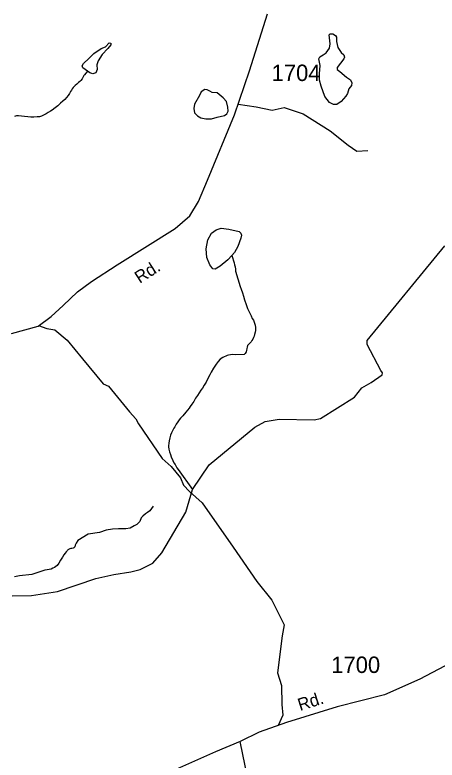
# Model space of a CAD drawing. Extents: x 2056842 to 2160602, y 826753 to 1016856.
# Drawn here: x 2114302 to 2117511, y 858411 to 864081 of the extents above; entities that cross this region are included whole.
import ezdxf

# ---------------------------------------------------------------- set-up
doc = ezdxf.new("R2010")
doc.units = 0
for name, color, linetype in [('Exist Hydrographic Creek Single Shore', 7, 'Continuous'), ('Exist Hydrographic Misc Water Feature', 7, 'Continuous'), ('Exist Road Non-System Type 51', 7, 'Continuous'), ('Exist Road Secondary Type 51 Attributed', 7, 'Continuous'), ('Exist Road Secondary Type 51 Label', 7, 'Continuous'), ('Exist Road Secondary Type 51 Number Label', 7, 'Continuous')]:
    doc.layers.add(name, color=color, linetype=linetype)

msp = doc.modelspace()

# ---------------------------------------------------------------- linework, layer by layer
at = {"layer": 'Exist Hydrographic Creek Single Shore'}
for points in [[(2114281.1, 859660), (2114427.1, 859662.3), (2114625.5, 859693.7), (2114916.8, 859793), (2115054.9, 859823.1), (2115184.3, 859843.2), (2115253.3, 859860.8), (2115350, 859909.8), (2115419.9, 859987.6), (2115601.8, 860298.8), (2115652.6, 860468.9), (2115778.2, 860657.4), (2116126, 860943.8), (2116205.1, 860987.8), (2116310.6, 861004.1), (2116576.8, 860999.1), (2116623.8, 861009.4), (2116883.2, 861173.8), (2116938.4, 861242.9), (2117010, 861284.3), (2117094.1, 861343.4), (2117095.4, 861358.4), (2117082.8, 861376), (2116978.6, 861572), (2116978.9, 861602.5), (2117571.4, 862322.8)], [(2115352.2, 860342.5), (2115327.1, 860308.5), (2115310.8, 860296), (2115294.5, 860285.5), (2115274.4, 860267), (2115260.5, 860254.9), (2115250.5, 860225.6), (2115229.1, 860204.3), (2115209, 860193), (2115177.7, 860175.4), (2115145, 860170.3), (2115088.5, 860171.6), (2115044.6, 860167.8), (2114996.8, 860160.3), (2114945.4, 860143.4), (2114858.7, 860130.9), (2114780.3, 860081.3), (2114766.3, 860061.1), (2114760.6, 860047), (2114756.5, 860035), (2114750.7, 860026.9), (2114745, 860024.6), (2114734.7, 860022.1), (2114726.9, 860020.8), (2114718.7, 860018.4), (2114704.8, 860010.8), (2114700.7, 860006.5), (2114690.9, 859996.2), (2114683.3, 859986.4), (2114673.2, 859971.7), (2114663.4, 859955.8), (2114649.4, 859933.5), (2114635.7, 859909.2), (2114622.2, 859891.9), (2114612.3, 859883.6), (2114602.3, 859877.4), (2114590.2, 859871.1), (2114577.3, 859864.5), (2114563.3, 859860.9), (2114548.1, 859858.8), (2114528.3, 859856.5), (2114430.5, 859822.8), (2114336.4, 859812.8), (2114298.7, 859805.2)]]:
    msp.add_lwpolyline(points, dxfattribs=at)
at = {"layer": 'Exist Hydrographic Misc Water Feature'}
for points in [[(2116816.5, 863463.5), (2116782.1, 863421.5), (2116750.3, 863398.6), (2116724.9, 863398.6), (2116694.3, 863413.9), (2116658.7, 863461), (2116629.4, 863538.7), (2116618, 863584.5), (2116616.7, 863632.9), (2116621.8, 863696.6), (2116612.9, 863746.2), (2116620.5, 863762.8), (2116644.7, 863776.8), (2116667.6, 863793.3), (2116694.3, 863827.7), (2116699.4, 863860.8), (2116691.8, 863928.3), (2116699.4, 863937.2), (2116718.5, 863936), (2116740.1, 863923.2), (2116747.8, 863910.5), (2116747.8, 863878.7), (2116756.7, 863832.8), (2116780.9, 863795.9), (2116802.5, 863778.1), (2116806.3, 863760.2), (2116801.2, 863746.2), (2116751.6, 863680), (2116752.9, 863664.7), (2116771.9, 863649.4), (2116822.9, 863606.1), (2116852.1, 863585.8), (2116862.3, 863565.4), (2116861, 863543.8), (2116840.7, 863518.3), (2116829.2, 863482.6), (2116816.5, 863463.5)], [(2114853.7, 863652.8), (2114817.3, 863679.2), (2114813.5, 863694.3), (2114822.3, 863711.9), (2114863.8, 863748.3), (2114902.7, 863788.5), (2114957.9, 863826.2), (2114989.3, 863837.5), (2115019.5, 863867.7), (2115030.8, 863865.2), (2115032, 863853.9), (2115008.2, 863825), (2114965.5, 863779.7), (2114935.3, 863730.7), (2114924, 863700.6), (2114926.5, 863666.7), (2114917.7, 863641.5), (2114893.9, 863631.5), (2114871.3, 863640.3), (2114853.7, 863652.8)], [(2114853.7, 863652.8), (2114830.7, 863624.5), (2114826.8, 863619.4), (2114821.3, 863609.7), (2114813.1, 863595.9), (2114803.4, 863583.2), (2114795.6, 863575), (2114785.8, 863567.2), (2114771.9, 863555.1), (2114760, 863544.7), (2114749.9, 863534.9), (2114743.8, 863528.5), (2114738.2, 863518.8), (2114731.9, 863509.2), (2114725.5, 863498), (2114716.5, 863482.3), (2114706, 863468.9), (2114694.3, 863452.4), (2114680.2, 863437.9), (2114666, 863424.2), (2114649, 863409.7), (2114627.1, 863389.9), (2114607.4, 863373.8), (2114583.8, 863357.1), (2114571.5, 863349.2), (2114553.7, 863339), (2114539.7, 863329.4), (2114524.6, 863319.9), (2114503.9, 863310.4), (2114488.3, 863305.9), (2114470, 863304.5), (2114445.8, 863304.2), (2114422, 863303.7), (2114399.1, 863304.3), (2114374.1, 863307.3), (2114351.7, 863311.1), (2114330, 863313.3), (2114314, 863313.7), (2114297.8, 863308.7)], [(2115797.2, 863291.3), (2115840.5, 863303.8), (2115896.3, 863315.2), (2115913.3, 863328.9), (2115922.4, 863349.4), (2115920.2, 863377.9), (2115909.9, 863421.2), (2115884.9, 863450.8), (2115840.5, 863487.3), (2115801.7, 863491.8), (2115784.7, 863499.8), (2115764.2, 863511.2), (2115746, 863512.3), (2115718.6, 863495.3), (2115706.1, 863469), (2115666.2, 863403), (2115661.7, 863368.8), (2115667.4, 863335.7), (2115689, 863313), (2115715.2, 863298.1), (2115752.8, 863291.3), (2115797.2, 863291.3)], [(2115950.2, 862250.5), (2115920.1, 862217.8), (2115862.3, 862170.1), (2115823.4, 862147.5), (2115807.1, 862150), (2115783.2, 862178.9), (2115761.9, 862235.4), (2115755.6, 862300.8), (2115768.2, 862368.6), (2115797, 862420.1), (2115830.9, 862446.5), (2115871.1, 862457.8), (2115928.9, 862451.5), (2116005.5, 862433.9), (2116020.5, 862420.1), (2116025.6, 862406.3), (2116020.5, 862381.2), (2115996.7, 862319.6), (2115970.3, 862274.4), (2115950.2, 862250.5)], [(2115950.2, 862250.5), (2115967.7, 862194.8), (2115971.4, 862179.2), (2115975.7, 862163.5), (2115977.8, 862145.4), (2115980, 862131.6), (2116015.3, 862013.5), (2116021, 861995.2), (2116031.5, 861965.7), (2116039.5, 861940), (2116047.9, 861913.7), (2116059.8, 861878.1), (2116070.7, 861846.1), (2116084.8, 861816), (2116098.7, 861790.3), (2116106.7, 861772.1), (2116115.1, 861759), (2116123.4, 861736.6), (2116127.9, 861720.1), (2116129.7, 861702.9), (2116129.7, 861690.7), (2116129.9, 861678.9), (2116127.9, 861667), (2116124, 861650.6), (2116120.3, 861636.4), (2116116.6, 861626.9), (2116110.2, 861614.5), (2116102.4, 861602.7), (2116096.7, 861594.2), (2116086.9, 861583.9), (2116078.9, 861574.2), (2116070.9, 861564.5), (2116067, 861554.1), (2116064.9, 861541.8), (2116063.1, 861527.9), (2116059, 861516.3), (2116053.2, 861504.2), (2116045.4, 861496.1), (2115975.7, 861495.3), (2115957.3, 861497.2), (2115941.7, 861495.2), (2115925.3, 861491.2), (2115916, 861488.9), (2115906, 861485.1), (2115893.7, 861480.5), (2115881.6, 861474.2), (2115861.9, 861460.6), (2115847.8, 861444.4), (2115832.2, 861424.5), (2115812.5, 861393.4), (2115794.9, 861363.6), (2115783.2, 861341.9), (2115769.4, 861315.5), (2115755.3, 861287.2), (2115741.5, 861262.9), (2115727.6, 861241.1), (2115716.1, 861225), (2115702.2, 861204.8), (2115690.3, 861185.4), (2115674.7, 861165.1), (2115660.8, 861140.8), (2115646.8, 861118.2), (2115634.9, 861100.5), (2115627.5, 861088.3), (2115601.5, 861058.1), (2115577.7, 861030.1), (2115561.9, 861013.8), (2115550.2, 860999.3), (2115539.8, 860985.9), (2115528.3, 860966.9), (2115516.4, 860947.7), (2115510.7, 860935.6), (2115502.2, 860921), (2115492.6, 860901.3), (2115484.8, 860882.7), (2115479.5, 860863.2), (2115475.4, 860841), (2115471.5, 860823), (2115469.9, 860802.6), (2115469.9, 860795.2), (2115471.9, 860777.1), (2115476.2, 860756.6), (2115484.4, 860736.7), (2115490.4, 860719.6), (2115502.9, 860689.6), (2115510.7, 860673), (2115519.1, 860659.6), (2115533.4, 860635.5), (2115543.3, 860621.4), (2115652.6, 860468.9)]]:
    msp.add_lwpolyline(points, dxfattribs=at)
at = {"layer": 'Exist Road Non-System Type 51'}
for points in [[(2115998.7, 863402.3), (2116137, 863381.2), (2116257.5, 863356.2), (2116348.9, 863377), (2116494.3, 863327.1), (2116697.8, 863198.3), (2116834.9, 863090.2), (2116901.4, 863044.5), (2116984.4, 863048.6)], [(2114482.3, 861717.4), (2114543.8, 861694.8), (2114606.1, 861684.4), (2114699.6, 861607.5), (2114815.9, 861464.1), (2114971.7, 861272.9), (2115013.2, 861256.3), (2115174.2, 861059.9), (2115222, 861007.9), (2115240.7, 860970.5), (2115421.4, 860706.5), (2115489.9, 860646.2), (2115559.5, 860560), (2115582.3, 860501.8), (2115630.1, 860454), (2115725.6, 860368.8), (2115960.3, 860032.1), (2116140, 859769.1), (2116256.3, 859627.8), (2116349.8, 859440.7), (2116333.2, 859355.5), (2116298.9, 859073.9), (2116328, 858978.3), (2116330.1, 858834.9), (2116338.4, 858751.7), (2116302.7, 858674.7)]]:
    msp.add_lwpolyline(points, dxfattribs=at)
at = {"layer": 'Exist Road Secondary Type 51 Attributed'}
for points in [[(2114276.4, 861656.4), (2114477.6, 861714), (2114577.3, 861786.8), (2114669.3, 861871.2), (2114776.6, 861974.8), (2114883.9, 862051.5), (2115078.4, 862179), (2115519.2, 862455.2), (2115630.4, 862553), (2115697.5, 862660.4), (2115765.5, 862822.4), (2115970.5, 863321.1), (2116086.5, 863655.7), (2116222.6, 864089.2)], [(2117802.8, 859251), (2117381, 859026.6), (2117111.1, 858906.8), (2116752.9, 858816.5), (2116365.3, 858696.7), (2116160, 858624.4), (2116014.7, 858553.1)], [(2116014.7, 858553.1), (2115826.8, 858472.9), (2115485.7, 858321.4), (2115251.9, 858237), (2114913.1, 858130.1), (2114433.5, 857983.9), (2114322.4, 857975.2), (2114007.6, 857961.3), (2113697.1, 857946), (2113575.9, 857915.8), (2113456.1, 857871.7), (2113270.2, 857776.8), (2112815.6, 857525), (2112231.5, 857213.9), (2112020.7, 857108.4), (2111803.4, 857028.1)], [(2116637.5, 853815.9), (2116693.1, 853947.6), (2116708.3, 854090.2), (2116706.4, 854192.9), (2116677.9, 854337.4), (2116557.2, 854697.7), (2116422.3, 855108.5), (2116183.8, 855856.7), (2116047.9, 856281.7), (2116021.3, 856416.7), (2116006.1, 856574.6), (2116006.1, 856806.6), (2116033.7, 857239.2), (2116047, 857341.8), (2116115.4, 857629), (2116125.8, 857774.5), (2116116.3, 857941.8), (2116068.8, 858282.2), (2116014.7, 858553.1)]]:
    msp.add_lwpolyline(points, dxfattribs=at)

# ---------------------------------------------------------------- texts
at = {"layer": 'Exist Road Secondary Type 51 Label'}
for rotation, p in [(32.7953, (2115250.8, 862033.9)), (17.6989, (2116469.5, 858783.7))]:
    msp.add_text('Rd.', height=95, rotation=rotation, dxfattribs=at).set_placement(p)
at = {"layer": 'Exist Road Secondary Type 51 Number Label'}
for s, p in [('1704', (2116253.4, 863577.9)), ('1700', (2116706.6, 859073.9))]:
    msp.add_text(s, height=125, dxfattribs=at).set_placement(p)

doc.saveas('drawing.dxf')
